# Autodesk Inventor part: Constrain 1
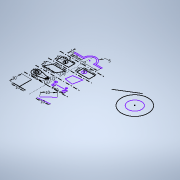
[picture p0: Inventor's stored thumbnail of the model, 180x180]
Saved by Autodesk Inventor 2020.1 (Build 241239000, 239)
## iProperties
Created: 2018-03
Part Number: Constrain 1
Material: Generic
Document SubType Name: Modeling
Designer: DUL
Density: 1 g/cm^3
Appearance: Default
Author: DUL
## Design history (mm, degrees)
sketch "Sketch1"
  geometry: L1 (-14.542, 2.317)-(-4.542, 2.317) reference; L2 (6.154, 3.448)-(13.548, 10.181); L3 (-9.542, 2.317)-(-9.542, 12.317) reference; L4 (5.715, 1.723)-(15.66, 2.773); L5 (-18.13, 14.671)-(18.13, 14.671) reference; L6 (-12.948, 19.414)-(-3.948, 19.414) reference; L7 (-12.281, 22.339)-(-3.725, 20.389) reference; L8 (-12.281, 16.49)-(-3.725, 18.439); L9 (4.516, 18.816)-(13.515, 18.991); L10 (-18.13, 24.076)-(18.13, 24.076) reference; L11 (-14.542, 26.88)-(-11.645, 31.88); L12 (-11.645, 31.88)-(-1.645, 31.88) reference; L13 (-1.645, 31.88)-(-4.542, 26.88) reference; L14 (-4.542, 26.88)-(-14.542, 26.88); L15 (3.663, 26.523)-(4.516, 31.88); L16 (4.516, 31.88)-(11.818, 32.954); L17 (11.818, 32.954)-(10.352, 25.622); L18 (10.352, 25.622)-(3.663, 26.523); L19 (-18.13, 34.382)-(18.13, 34.382) reference; L20 (-13.093, 41.103)-(-3.093, 41.103) reference; L21 (-3.093, 41.103)-(-3.093, 36.103) reference; L22 (-3.093, 36.103)-(-13.093, 36.103); L23 (-13.093, 36.103)-(-13.093, 41.103); L24 (3.663, 41.103)-(13.663, 41.103) reference; L25 (13.663, 41.103)-(13.663, 36.103) reference; L26 (13.663, 36.103)-(3.663, 36.103); L27 (3.663, 36.103)-(3.663, 41.103); L28 (0, 0)-(0, 53.782); L29 (-18.13, 44.046)-(18.13, 44.046) reference; L30 (-10.84, 49.476)-(-3.967, 49.476); L31 (6.033, 49.476)-(11.16, 49.476); L32 (-10.84, 48.476)-(-2.84, 48.476); L33 (4.906, 48.476)-(11.16, 48.476); L34 (-10.84, 49.476)-(-10.84, 48.476); L35 (11.16, 49.476)-(11.16, 48.476); L36 (30.316, 38.266)-(41.221, 44.987) reference; L37 (33.889, 40.468)-(45.737, 47.771); C1 r 1.5 at (-12.948, 19.414) reference; C2 r 0.5 at (-3.948, 19.414) reference; C3 r 1.027 at (2.135, 20.389); C4 r 1.058 at (3.163, 17.465); C5 r 0.669 at (10.866, 20.389); C6 r 1.153 at (12.082, 17.217); C7 r 1.5 at (-8.093, 38.603) reference; C8 r 1.5 at (6.815, 38.948); C9 r 5.596 at (51.2, 36.103); C10 r 10.89 at (51.2, 36.103) reference; A1 r 3 centre (-12.948, 19.414) between (-12.281, 22.339) and (-12.281, 16.49) reference; A2 r 1 centre (-3.948, 19.414) between (-3.725, 20.389) and (-3.725, 18.439); A3 r 5 centre (1.033, 49.476) between (6.033, 49.476) and (-3.967, 49.476); A4 r 4 centre (1.033, 49.476) between (4.906, 48.476) and (-2.84, 48.476); 1 further point
  constraints: 74 end point, 18 horizontal, 14 centre point, 8 point on circle, 7 vertical, 5 parallel, 4 tangent, 3 coincident, 3 point on line, 2 midpoint, 2 perpendicular, 1 collinear, 1 concentric, 1 vertical alignment, 10 other
  dimensions: "d1" = 10 distance of L1.start L1.end; "d4" = 10 distance of L2.start L2.end; "d6" = 10 vertical distance of L1.start L3.end; "d7" = 10 distance of L4.start L4.end; "d13" = 9 distance of L6.start L6.end; "d15" = 6 diameter of A1 (derived); "d16" = 3 diameter of C1 (derived); "d17" = 2 diameter of A2 (derived); "d18" = 1 diameter of C2 (derived); "d21" = 9 distance of L9.start L9.end; "d22" = 10 distance of L13.end L11.start; "d23" = 5 vertical distance of L11.start L11.end; "d24" = 10 distance of L11.end L12.end; "d25" = 5 vertical distance of L12.end L13.end (derived); "d26" = 10 distance of L20.start L20.end; "d27" = 5 distance of L22.end L20.start; "d29" = 3 diameter of C7 (derived); "d30" = 10 distance of L24.start L24.end; "d31" = 5 distance of L26.end L24.start; "d32" = 3 diameter of C8; "d33" = 1 distance between parallel lines of L30 L32; "d34" = 5 radius of A3; "d35" = 8 distance of L32.start L32.end; "d37" = 22 distance between parallel lines of L35 L34
